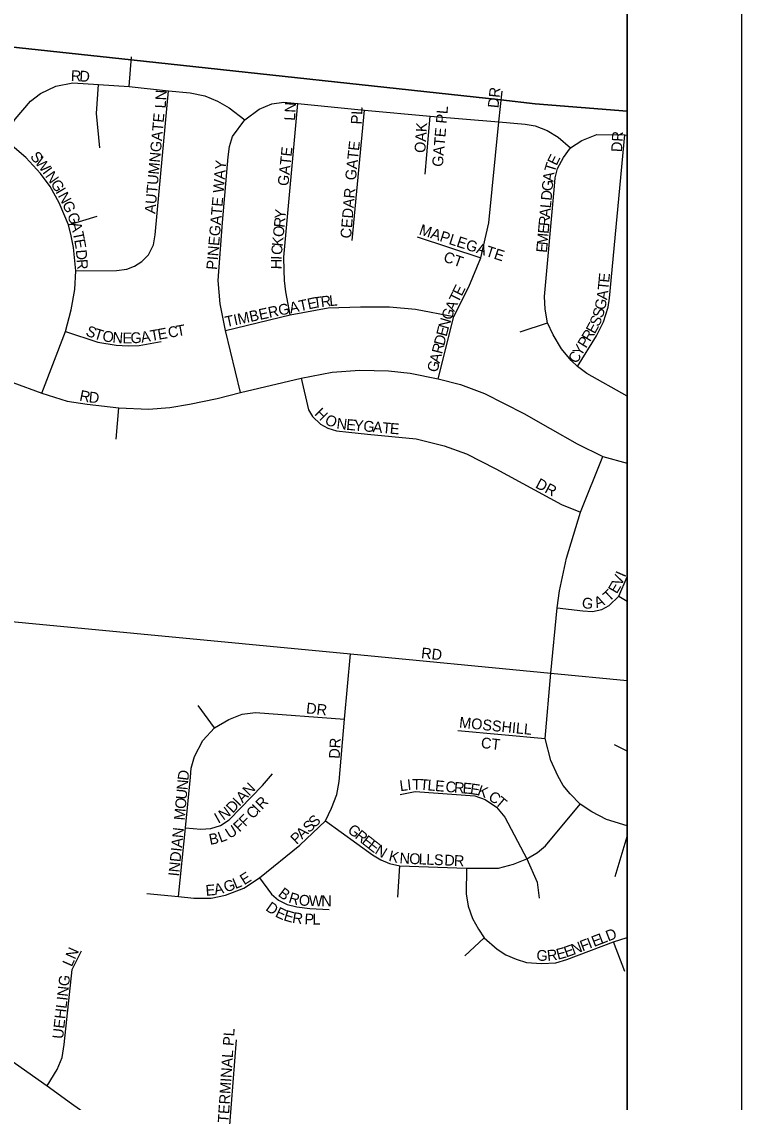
# Model space of a CAD drawing. Extents: x 8.5 to 81.5, y -1.2 to 22.4.
# Drawn here: x 55.722 to 56.353, y 18.242 to 19.189 of the extents above; entities that cross this region are included whole.
import ezdxf

# ---------------------------------------------------------------- set-up
doc = ezdxf.new("R2010")
doc.units = 0
for name, color, linetype in [('GM_X_Adjacent_County', 7, 'Continuous'), ('GM_X_City_Street', 7, 'Continuous'), ('GM_X_City_Street_Text', 7, 'Continuous'), ('GM_X_Corporation', 7, 'Continuous'), ('GM_X_County', 7, 'Continuous'), ('SH_Data', 7, 'Continuous')]:
    doc.layers.add(name, color=color, linetype=linetype)

msp = doc.modelspace()

# ---------------------------------------------------------------- linework, layer by layer
at = {"layer": 'GM_X_Adjacent_County'}
for points in [[(54.08792, 21.25055), (53.97517, 21.07964), (53.98925, 20.88787), (54.01131, 20.79217), (54.0509, 20.40525), (54.08743, 20.21352), (54.08516, 20.02178), (54.11826, 19.92611), (54.16353, 19.83082), (54.25825, 19.73401), (54.36439, 19.53926), (54.43857, 19.4436), (54.4557, 19.28681), (54.60716, 19.27259), (55.07099, 19.22961), (55.57538, 19.18184), (55.8177, 19.15565), (56.1419, 19.12062), (56.17199, 19.11737), (56.25272, 19.11082)], [(56.25272, 19.11082), (56.25272, 21.25055), (54.08792, 21.25055)]]:
    msp.add_lwpolyline(points, dxfattribs=at)
at = {"layer": 'GM_X_City_Street'}
for points in [[(55.81595, 19.1323), (55.81795, 19.15846)], [(55.57169, 19.07164), (55.58369, 19.07004), (55.61533, 19.06632), (55.63356, 19.06446), (55.64763, 19.06333), (55.66318, 19.06333), (55.67948, 19.06707), (55.69249, 19.07514), (55.70565, 19.08725), (55.71609, 19.10365), (55.72942, 19.11965), (55.7381, 19.12632), (55.75171, 19.13271), (55.76667, 19.13571), (55.7891, 19.13416), (55.81595, 19.1323), (55.8506, 19.12851), (55.8694, 19.12674), (55.88226, 19.12419), (55.89348, 19.11971), (55.90379, 19.11373), (55.91729, 19.10309)], [(55.79027, 19.07875), (55.78733, 19.10872), (55.7891, 19.13416)], [(55.76918, 18.97077), (55.80484, 18.97116), (55.81385, 18.97241), (55.82059, 18.97492), (55.82701, 18.97907), (55.83282, 18.98487), (55.8372, 18.99357), (55.83867, 19.00231), (55.8423, 19.04027), (55.8506, 19.12851)], [(56.08674, 18.87609), (56.10053, 18.93083), (56.11368, 18.95678), (56.12425, 18.98233), (56.1314, 19.01299), (56.14009, 19.10156), (56.14289, 19.12844)], [(55.91368, 18.86416), (55.90037, 18.9185), (55.89582, 18.942), (55.8941, 18.96238), (55.89786, 19.01332), (55.90287, 19.07068), (55.90401, 19.07975), (55.90648, 19.08855), (55.91729, 19.10309), (55.92999, 19.11268), (55.94114, 19.11732), (55.95153, 19.11876), (55.9638, 19.11757), (56.02222, 19.11161), (56.07979, 19.1065), (56.14009, 19.10156), (56.16325, 19.09935), (56.17194, 19.09781), (56.18233, 19.09372), (56.19221, 19.08811), (56.20277, 19.07874)], [(55.95702, 18.93232), (55.95342, 18.95248), (55.95225, 18.96233), (55.9518, 18.97145), (55.95151, 18.98277), (55.9638, 19.11757)], [(56.01134, 18.99731), (56.02222, 19.11161)], [(56.07553, 19.05557), (56.07979, 19.1065)], [(55.73939, 18.86377), (55.76029, 18.91778), (55.76526, 18.9366), (55.7684, 18.95462), (55.76918, 18.97077), (55.76715, 18.99145), (55.76511, 19.00148), (55.76291, 19.01104), (55.75461, 19.03032), (55.74677, 19.04474), (55.73831, 19.05618), (55.7253, 19.07029), (55.70565, 19.08725)], [(56.25272, 18.86117), (56.21711, 18.88102), (56.20904, 18.88707), (56.20357, 18.89239), (56.19493, 18.90248), (56.18759, 18.91486), (56.18269, 18.92537), (56.18082, 18.93732), (56.18024, 18.94841), (56.18888, 19.04503), (56.18946, 19.05252), (56.19162, 19.06059), (56.19666, 19.07024), (56.20277, 19.07874), (56.21279, 19.08507), (56.22611, 19.09049), (56.25066, 19.08996), (56.25272, 19.08976)], [(56.20904, 18.88707), (56.2256, 18.91378), (56.23194, 18.92631), (56.23597, 18.93898), (56.23698, 18.94704), (56.25066, 19.08996)], [(55.76291, 19.01104), (55.78784, 19.01872)], [(56.06855, 19.00072), (56.12425, 18.98233)], [(55.90037, 18.9185), (55.95702, 18.93232), (55.99042, 18.93837), (56.01889, 18.93927), (56.04423, 18.93927), (56.06687, 18.93726), (56.10053, 18.93083)], [(56.15865, 18.91731), (56.18269, 18.92537)], [(55.76029, 18.91778), (55.78846, 18.90823), (55.8046, 18.90572), (55.8151, 18.90509), (55.82467, 18.90557), (55.84411, 18.90894)], [(55.68813, 18.88248), (55.73939, 18.86377), (55.76163, 18.85679), (55.77921, 18.85409), (55.80699, 18.85077), (55.83292, 18.84954), (55.85173, 18.85101), (55.86884, 18.85412), (55.89303, 18.85888), (55.91368, 18.86416), (55.96679, 18.87693), (55.99406, 18.88199), (56.01815, 18.88383), (56.04335, 18.88322), (56.06236, 18.88128), (56.08674, 18.87609)], [(55.96679, 18.87693), (55.97321, 18.84908), (55.97683, 18.84334), (55.98364, 18.83638), (55.99013, 18.83291), (55.99784, 18.83064), (56.00842, 18.82959), (56.02504, 18.82777), (56.0675, 18.82354), (56.09228, 18.8175), (56.11178, 18.81055), (56.13746, 18.7974), (56.19488, 18.76597), (56.2118, 18.75944)], [(56.08674, 18.87609), (56.10653, 18.87117), (56.12742, 18.8633), (56.16196, 18.84573), (56.18507, 18.83282), (56.20879, 18.8193), (56.23139, 18.80818), (56.25272, 18.80223)], [(55.80445, 18.82336), (55.80699, 18.85077)], [(56.25272, 18.48461), (56.23448, 18.4901), (56.22152, 18.49666), (56.21142, 18.50339), (56.2025, 18.51248), (56.19661, 18.5198), (56.19165, 18.5283), (56.18568, 18.5416), (56.18062, 18.56087), (56.18568, 18.61835), (56.19131, 18.67549), (56.19316, 18.69031), (56.19933, 18.71919), (56.2118, 18.75944), (56.23139, 18.80818)], [(56.19131, 18.67549), (56.21366, 18.67291), (56.22227, 18.67245), (56.23041, 18.67404), (56.23678, 18.67759), (56.2453, 18.68574), (56.25272, 18.7026)], [(55.53496, 18.68057), (56.00995, 18.63533), (56.18568, 18.61835), (56.25272, 18.61175)], [(56.2453, 18.68574), (56.25272, 18.68134)], [(55.83143, 18.42512), (55.85916, 18.42248), (55.8728, 18.42101), (55.88776, 18.42116), (55.90037, 18.42365), (55.91651, 18.42996), (55.93034, 18.43886), (55.96551, 18.46751), (55.98816, 18.48895), (55.99323, 18.49993), (55.99792, 18.51196), (55.99998, 18.52326), (56.00482, 18.57782), (56.00995, 18.63533)], [(55.85916, 18.42248), (55.86541, 18.4828), (55.86962, 18.52725), (55.87027, 18.53502), (55.87328, 18.54528), (55.88053, 18.55925), (55.8908, 18.57038), (55.90328, 18.57759), (55.91491, 18.58222), (55.92683, 18.5839), (56.00482, 18.57782)], [(55.8908, 18.57038), (55.87648, 18.58987)], [(56.10421, 18.56813), (56.18062, 18.56087)], [(56.25272, 18.54982), (56.24135, 18.55551)], [(55.86541, 18.4828), (55.87887, 18.48169), (55.88757, 18.48211), (55.89598, 18.48463), (55.90355, 18.48968), (55.93286, 18.51983), (55.94169, 18.52992)], [(56.05347, 18.51191), (56.06676, 18.51462), (56.11893, 18.51064), (56.12817, 18.50756), (56.13815, 18.50074), (56.14527, 18.49195), (56.16452, 18.45564)], [(55.98816, 18.48895), (56.02939, 18.45906), (56.03652, 18.45461), (56.04424, 18.45134), (56.05336, 18.44935), (56.11169, 18.44736), (56.13976, 18.44725), (56.15297, 18.45087), (56.16452, 18.45564), (56.17394, 18.46106), (56.18085, 18.467), (56.21142, 18.50339)], [(56.24217, 18.44012), (56.25272, 18.47507)], [(56.16452, 18.45564), (56.17366, 18.43521), (56.17553, 18.42106)], [(56.05149, 18.422), (56.05336, 18.44935)], [(56.11169, 18.44736), (56.11153, 18.42496), (56.11332, 18.41394), (56.1169, 18.40321), (56.12213, 18.39385), (56.12731, 18.38623), (56.13851, 18.37637), (56.14635, 18.37142), (56.1553, 18.3677), (56.16424, 18.36481), (56.17745, 18.36384), (56.19012, 18.36453), (56.19975, 18.36742), (56.24047, 18.38266), (56.25272, 18.38665)], [(55.93034, 18.43886), (55.94084, 18.42451), (55.94682, 18.41931), (55.95462, 18.41565), (55.963, 18.41334), (55.97447, 18.41208), (55.99133, 18.41121)], [(56.11029, 18.37045), (56.12731, 18.38623)], [(55.57353, 18.37577), (55.57986, 18.37183), (55.61551, 18.34747), (55.66625, 18.31115), (55.74396, 18.25649), (55.76539, 18.24108), (55.77957, 18.23131), (55.79264, 18.22401), (55.80461, 18.21865), (55.81782, 18.21383), (55.83282, 18.21053), (55.90274, 18.20337), (56.02308, 18.19186), (56.16825, 18.17705), (56.25272, 18.16886)], [(56.25053, 18.35669), (56.24047, 18.38266)], [(55.74396, 18.25649), (55.75283, 18.27097), (55.75715, 18.2815), (55.75897, 18.2929), (55.76606, 18.3585), (55.77414, 18.37506)], [(55.90274, 18.20337), (55.90998, 18.29686)]]:
    msp.add_lwpolyline(points, dxfattribs=at)
at = {"layer": 'GM_X_Corporation'}
msp.add_line((56.25272, 15.06706), (56.25272, 20.11042), dxfattribs=at)
at = {"layer": 'GM_X_County'}
for points in [[(54.08792, 21.25055), (49.45272, 21.25055), (49.45272, 14.45055), (56.25272, 14.45055), (56.25272, 19.11082)], [(56.25272, 19.11082), (56.17199, 19.11737), (56.1419, 19.12062), (55.8177, 19.15565), (55.57538, 19.18184), (55.07099, 19.22961), (54.60716, 19.27259), (54.4557, 19.28681), (54.43857, 19.4436), (54.36439, 19.53926), (54.25825, 19.73401), (54.16353, 19.83082), (54.11826, 19.92611), (54.08516, 20.02178), (54.08743, 20.21352), (54.0509, 20.40525), (54.01131, 20.79217), (53.98925, 20.88787), (53.97517, 21.07964), (54.08792, 21.25055)]]:
    msp.add_lwpolyline(points, dxfattribs=at)
at = {"layer": 'SH_Data'}
for p, q in [((56.35272, 21.35055), (56.35272, 14.35055)), ((56.25272, 21.25055), (56.25272, 14.45055))]:
    msp.add_line(p, q, dxfattribs=at)

# ---------------------------------------------------------------- texts
at = {"layer": 'GM_X_City_Street_Text'}
for s, height, rotation, p in [('R', 0.00947, 357.40075, (55.76466, 19.13728)), ('D', 0.00947, 356.67589, (55.77212, 19.13694)), ('LN', 0.00947, 86.98901, (55.848, 19.11309)), ('DR', 0.00947, 83.99458, (56.13968, 19.11318)), ('LN', 0.00947, 86.82218, (55.96134, 19.10226)), ('GATE PL', 0.00947, 84.98608, (56.0909, 19.06173)), ('AUTUMNGATE', 0.00947, 84.75211, (55.83883, 19.02062)), ('PL', 0.00947, 86.18785, (56.01967, 19.09895)), ('OAK', 0.00947, 86.18108, (56.0755, 19.07395)), ('DR', 0.00947, 86.82218, (56.248, 19.07476)), ('GATE', 0.00947, 83.93096, (55.95551, 19.04485)), ('GATE', 0.00947, 83.92636, (56.01467, 19.04985)), ('S', 0.00947, 309.03953, (55.72866, 19.07079)), ('W', 0.00947, 308.61518, (55.73285, 19.06563)), ('PINEGATE WAY', 0.0094697, 85.10208, (55.893, 18.97146)), ('E', 0.00947, 64.1314, (56.19061, 19.06249)), ('I', 0.00947, 306.18805, (55.73954, 19.05725)), ('N', 0.00947, 305.16929, (55.74198, 19.05392)), ('T', 0.00947, 73.08612, (56.18882, 19.05648)), ('G', 0.00947, 302.09573, (55.7467, 19.04722)), ('G', 0.00947, 84.8679, (56.18702, 19.04043)), ('A', 0.00947, 82.08621, (56.18775, 19.0486)), ('I', 0.00947, 300.69386, (55.7511, 19.04021)), ('N', 0.00947, 298.28596, (55.75318, 19.03672)), ('CEDAR', 0.00947, 85.13361, (56.0105, 18.99898)), ('D', 0.00947, 84.85701, (56.18628, 19.03212)), ('G', 0.00947, 294.01353, (55.75704, 19.02955)), ('L', 0.00947, 84.86035, (56.18568, 19.02548)), ('G', 0.00947, 291.85824, (55.76138, 19.01972)), ('Y', 0.00947, 84.39596, (55.95288, 19.01594)), ('A', 0.00947, 84.85701, (56.18493, 19.01718)), ('A', 0.00947, 284.08395, (55.76438, 19.01231)), ('R', 0.00947, 84.41035, (55.95215, 19.00848)), ('MAPLEGATE', 0.00947, 341.99559, (56.0695, 19.00303)), ('E', 0.00947, 84.86035, (56.18366, 19.00307)), ('R', 0.00947, 84.86932, (56.18426, 19.00971)), ('T', 0.00947, 281.66355, (55.76638, 19.00433)), ('O', 0.00947, 84.39596, (55.95134, 19.00018)), ('M', 0.00947, 84.85527, (56.18277, 18.99311)), ('E', 0.00947, 280.30241, (55.76772, 18.99786)), ('C', 0.00947, 85.08915, (55.94989, 18.98444)), ('K', 0.00947, 84.41771, (55.95053, 18.99189)), ('E', 0.00947, 84.8575, (56.18217, 18.98647)), ('D', 0.00947, 274.92336, (55.76919, 18.98906)), ('I', 0.00947, 87.46295, (55.94971, 18.98039)), ('CT', 0.00947, 340.5566, (56.09078, 18.97932)), ('R', 0.00947, 274.449, (55.7699, 18.98077)), ('H', 0.00947, 89.67209, (55.94966, 18.97215)), ('E', 0.00947, 84.45291, (56.23675, 18.96026)), ('E', 0.00947, 63.43494, (56.1074, 18.94808)), ('A', 0.00947, 82.62101, (56.23498, 18.94503)), ('T', 0.00947, 84.30067, (56.23609, 18.9536)), ('TIMBERGATE', 0.00947, 12.18158, (55.90104, 18.9214)), ('T', 0.00947, 7.53506, (55.97787, 18.9381)), ('R', 0.00947, 6.89004, (55.98445, 18.93897)), ('L', 0.00947, 5.52842, (55.99184, 18.93986)), ('T', 0.00947, 63.43494, (56.10442, 18.94211)), ('G', 0.00947, 77.23791, (56.23297, 18.93595)), ('G', 0.00947, 69.48285, (56.09814, 18.92697)), ('A', 0.00947, 65.45091, (56.101, 18.93462)), ('S', 0.00947, 74.29146, (56.23104, 18.92901)), ('N', 0.00947, 73.51479, (56.09584, 18.91915)), ('E', 0.00947, 61.29337, (56.22412, 18.91497)), ('S', 0.00947, 64.80576, (56.2276, 18.92138)), ('S', 0.00947, 337.1637, (55.77716, 18.91463)), ('T', 0.00947, 342.7548, (55.78425, 18.9117)), ('O', 0.00947, 350.88802, (55.79205, 18.90939)), ('N', 0.00947, 355.48809, (55.8011, 18.90797)), ('E', 0.00947, 0.1204, (55.81024, 18.90728)), ('G', 0.00947, 2.48399, (55.81733, 18.90731)), ('A', 0.00947, 9.50012, (55.82692, 18.9078)), ('T', 0.00947, 10.19631, (55.83526, 18.9092)), ('E', 0.00947, 10.20999, (55.84183, 18.91038)), ('C', 0.00947, 10.20493, (55.85085, 18.912)), ('T', 0.00947, 10.18999, (55.85823, 18.91333)), ('E', 0.00947, 75.53076, (56.09419, 18.91278)), ('R', 0.00947, 58.684, (56.21998, 18.90815)), ('R', 0.00947, 75.53076, (56.09024, 18.89745)), ('D', 0.00947, 75.53076, (56.09211, 18.90471)), ('Y', 0.00947, 58.62016, (56.21216, 18.89533)), ('P', 0.00947, 58.6287, (56.2165, 18.90245)), ('A', 0.00947, 75.53076, (56.08816, 18.88938)), ('C', 0.00947, 58.628, (56.20826, 18.88893)), ('G', 0.00947, 75.53076, (56.08607, 18.88132)), ('R', 0.00947, 348.90441, (55.7719, 18.85722)), ('D', 0.00947, 354.3582, (55.78021, 18.85564)), ('H', 0.00947, 314.87639, (55.9779, 18.84509)), ('O', 0.00947, 334.62918, (55.98668, 18.83713)), ('N', 0.00947, 353.1184, (55.99741, 18.83264)), ('E', 0.00947, 354.77191, (56.00597, 18.83161)), ('Y', 0.00947, 354.94725, (56.01264, 18.831)), ('G', 0.00947, 354.96973, (56.02095, 18.83027)), ('A', 0.00947, 354.96973, (56.02925, 18.82954)), ('T', 0.00947, 354.9735, (56.03755, 18.82881)), ('E', 0.00947, 354.93914, (56.04419, 18.82822)), ('DR', 0.00947, 332.10332, (56.17144, 18.78124)), ('I', 0.00947, 66.48404, (56.25071, 18.7017)), ('E', 0.00947, 59.67205, (56.24343, 18.68723)), ('V', 0.00947, 66.19323, (56.24733, 18.69403)), ('T', 0.00947, 43.92773, (56.23688, 18.68038)), ('G', 0.00947, 353.62601, (56.21252, 18.67541)), ('A', 0.00947, 21.57921, (56.22576, 18.67515)), ('RD', 0.00947, 353.98321, (56.07163, 18.63144)), ('DR', 0.00947, 353.99459, (55.9708, 18.5831)), ('MOSSHILL', 0.00947, 354.20725, (56.10496, 18.5706)), ('DR', 0.00947, 86.97694, (56.0005, 18.54309)), ('CT', 0.00947, 353.65048, (56.12401, 18.55275)), ('D', 0.00947, 82.87769, (55.86775, 18.52375)), ('N', 0.00947, 84.92476, (55.86702, 18.51554)), ('N', 0.00947, 45.94273, (55.92119, 18.51005)), ('L', 0.00947, 7.28769, (56.05369, 18.51476)), ('I', 0.00947, 6.26296, (56.06026, 18.5156)), ('T', 0.00947, 0.30055, (56.06414, 18.51604)), ('T', 0.00947, 355.70608, (56.07061, 18.51608)), ('L', 0.00947, 355.13201, (56.07723, 18.51559)), ('E', 0.00947, 355.16486, (56.08388, 18.51502)), ('C', 0.00947, 355.13754, (56.09302, 18.51425)), ('R', 0.00947, 355.14979, (56.10049, 18.51361)), ('E', 0.00947, 355.13201, (56.10796, 18.51298)), ('E', 0.00947, 351.3909, (56.11444, 18.51243)), ('K', 0.00947, 340.15507, (56.12056, 18.51156)), ('O', 0.00947, 84.92232, (55.86555, 18.49894)), ('U', 0.00947, 84.92476, (55.86629, 18.50724)), ('I', 0.00947, 45.92703, (55.91249, 18.50107)), ('A', 0.00947, 45.93907, (55.91539, 18.50406)), ('R', 0.00947, 45.85868, (55.93249, 18.49825)), ('C', 0.00947, 326.47831, (56.13007, 18.50781)), ('T', 0.00947, 319.68022, (56.13608, 18.50384)), ('M', 0.00947, 84.92925, (55.86467, 18.48898)), ('N', 0.00947, 35.95277, (55.8986, 18.48893)), ('D', 0.00947, 46.32146, (55.90675, 18.49505)), ('C', 0.00947, 45.82798, (55.92436, 18.48988)), ('I', 0.00947, 45.84987, (55.92959, 18.49526)), ('I', 0.00947, 29.28392, (55.89395, 18.48624)), ('F', 0.00947, 43.41167, (55.91272, 18.47852)), ('F', 0.00947, 44.69214, (55.91773, 18.48326)), ('S', 0.00947, 43.14387, (55.97368, 18.4779)), ('S', 0.00947, 43.12623, (55.97854, 18.48246)), ('INDIAN', 0.00947, 84.17239, (55.85967, 18.43985)), ('U', 0.00947, 31.69101, (55.90396, 18.47285)), ('A', 0.00947, 43.12946, (55.9676, 18.4722)), ('G', 0.00947, 321.72248, (56.00672, 18.47939)), ('R', 0.00947, 321.71184, (56.01327, 18.47423)), ('B', 0.00947, 11.16707, (55.88693, 18.4677)), ('L', 0.00947, 20.6228, (55.89592, 18.46962)), ('P', 0.00947, 43.14491, (55.96274, 18.46764)), ('E', 0.00947, 321.69855, (56.01915, 18.46958)), ('E', 0.00947, 321.72564, (56.02439, 18.46544)), ('N', 0.00947, 328.81687, (56.03067, 18.46058)), ('K', 0.00947, 346.39895, (56.04294, 18.4539)), ('N', 0.00947, 356.14233, (56.05277, 18.45168)), ('O', 0.00947, 357.51582, (56.06134, 18.45111)), ('L', 0.00947, 357.57932, (56.06967, 18.45074)), ('L', 0.00947, 357.56742, (56.07633, 18.45046)), ('S', 0.00947, 357.56742, (56.08299, 18.45018)), ('D', 0.00947, 357.58336, (56.09216, 18.44978)), ('R', 0.00947, 357.57058, (56.10049, 18.44943)), ('E', 0.00947, 32.14668, (55.91681, 18.43228)), ('E', 0.00947, 4.45737, (55.88331, 18.42312)), ('A', 0.00947, 12.22104, (55.89134, 18.42384)), ('G', 0.00947, 19.24631, (55.9007, 18.42595)), ('L', 0.00947, 22.71356, (55.90915, 18.42892)), ('B', 0.00947, 322.96009, (55.94586, 18.42357)), ('R', 0.00947, 343.35514, (55.95512, 18.4174)), ('O', 0.00947, 355.20641, (55.9644, 18.41486)), ('W', 0.00947, 359.06438, (55.9734, 18.41413)), ('N', 0.00947, 0.01536, (55.9844, 18.41394)), ('D', 0.00947, 324.59443, (55.93496, 18.41094)), ('E', 0.00947, 334.96349, (55.94334, 18.40518)), ('E', 0.00947, 343.3618, (55.95077, 18.40183)), ('R', 0.00947, 351.26749, (55.95852, 18.39961)), ('P', 0.00947, 357.36961, (55.96951, 18.39822)), ('L', 0.00947, 359.47302, (55.97654, 18.3979)), ('F', 0.00947, 21.10598, (56.2134, 18.37433)), ('I', 0.00947, 21.10055, (56.21962, 18.37673)), ('E', 0.00947, 21.12998, (56.22351, 18.37823)), ('L', 0.00947, 21.09634, (56.22973, 18.38064)), ('D', 0.00947, 21.09436, (56.23595, 18.38304)), ('LN', 0.00947, 66.03638, (55.76565, 18.36039)), ('G', 0.00947, 357.02627, (56.17285, 18.36639)), ('R', 0.00947, 5.98372, (56.18279, 18.366)), ('E', 0.00947, 14.63273, (56.19178, 18.36706)), ('E', 0.00947, 19.71161, (56.19911, 18.36902)), ('N', 0.00947, 20.94366, (56.20559, 18.37134)), ('UEHLING', 0.00947, 83.55845, (55.758, 18.29737)), ('TERMINAL PL', 0.0094697, 86.22991, (55.90304, 18.22395))]:
    msp.add_text(s, height=height, rotation=rotation, dxfattribs=at).set_placement(p)

doc.saveas('drawing.dxf')
